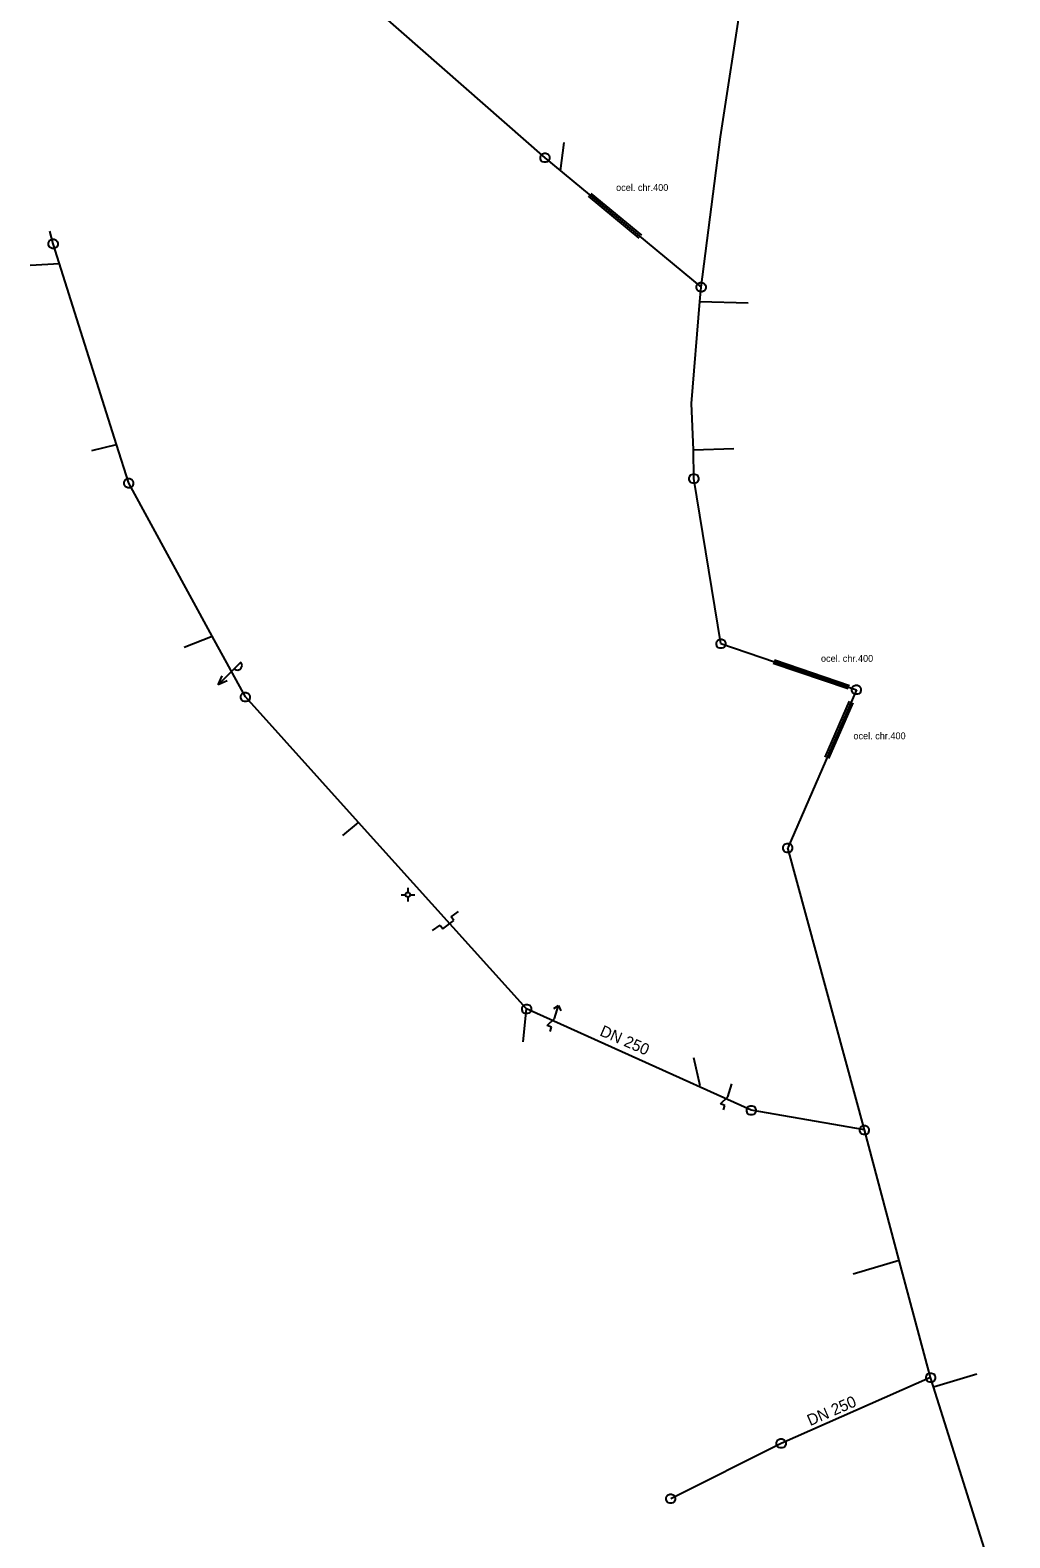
# Model space of a CAD drawing. Extents: x -717256 to -716843, y -1145423 to -1142840.
# Drawn here: x -717224 to -717116.2, y -1144391.3 to -1144225.5 of the extents above; entities that cross this region are included whole.
import ezdxf

# ---------------------------------------------------------------- set-up
doc = ezdxf.new("R2010")
doc.units = 0
for name, color, linetype in [('Vrstva 29', 7, 'Continuous'), ('Vrstva 30', 7, 'Continuous'), ('Vrstva 31', 7, 'Continuous'), ('Vrstva 9', 7, 'Continuous')]:
    doc.layers.add(name, color=color, linetype=linetype)

msp = doc.modelspace()

# ---------------------------------------------------------------- linework, layer by layer
at = {"layer": 'Vrstva 29'}
for p, q in [((-717162.308, -1144243.433), (-717156.744, -1144248.041)), ((-717156.999, -1144248.349), (-717162.564, -1144243.741)), ((-717142.113, -1144294.741), (-717133.851, -1144297.547)), ((-717133.98, -1144297.925), (-717142.242, -1144295.12)), ((-717136.528, -1144305.439), (-717133.86, -1144299.289)), ((-717133.493, -1144299.448), (-717136.161, -1144305.598))]:
    msp.add_line(p, q, dxfattribs=at)
at = {"layer": 'Vrstva 30'}
for p, q in [((-717193.377, -1144216.671), (-717167.355, -1144239.514)), ((-717148.036, -1144237.218), (-717145.608, -1144221.417)), ((-717150.172, -1144253.744), (-717148.036, -1144237.218)), ((-717167.855, -1144239.414), (-717167.805, -1144239.264)), ((-717167.855, -1144239.614), (-717167.855, -1144239.414)), ((-717167.755, -1144239.864), (-717167.855, -1144239.614)), ((-717167.805, -1144239.264), (-717167.705, -1144239.114)), ((-717167.605, -1144239.964), (-717167.755, -1144239.864)), ((-717167.705, -1144239.114), (-717167.455, -1144239.014)), ((-717167.455, -1144240.014), (-717167.605, -1144239.964)), ((-717167.455, -1144239.014), (-717167.255, -1144239.014)), ((-717167.255, -1144240.014), (-717167.455, -1144240.014)), ((-717167.355, -1144239.514), (-717150.172, -1144253.744)), ((-717167.255, -1144239.014), (-717167.005, -1144239.114)), ((-717167.105, -1144239.964), (-717167.255, -1144240.014)), ((-717166.955, -1144239.864), (-717167.105, -1144239.964)), ((-717167.005, -1144239.114), (-717166.905, -1144239.264)), ((-717166.855, -1144239.614), (-717166.955, -1144239.864)), ((-717166.905, -1144239.264), (-717166.855, -1144239.414)), ((-717166.855, -1144239.414), (-717166.855, -1144239.614)), ((-717221.9, -1144248.73), (-717221.8, -1144248.58)), ((-717221.8, -1144248.58), (-717221.55, -1144248.48)), ((-717221.55, -1144248.48), (-717221.35, -1144248.48)), ((-717221.35, -1144248.48), (-717221.1, -1144248.58)), ((-717221.1, -1144248.58), (-717221, -1144248.73)), ((-717221.95, -1144248.88), (-717221.9, -1144248.73)), ((-717221.95, -1144249.08), (-717221.95, -1144248.88)), ((-717221.85, -1144249.33), (-717221.95, -1144249.08)), ((-717221.7, -1144249.43), (-717221.85, -1144249.33)), ((-717221.55, -1144249.48), (-717221.7, -1144249.43)), ((-717221.35, -1144249.48), (-717221.55, -1144249.48)), ((-717214.472, -1144271.053), (-717221.45, -1144248.98)), ((-717221.2, -1144249.43), (-717221.35, -1144249.48)), ((-717221.05, -1144249.33), (-717221.2, -1144249.43)), ((-717220.95, -1144249.08), (-717221.05, -1144249.33)), ((-717221, -1144248.73), (-717220.95, -1144248.88)), ((-717220.95, -1144248.88), (-717220.95, -1144249.08)), ((-717150.672, -1144253.644), (-717150.622, -1144253.494)), ((-717150.622, -1144253.494), (-717150.522, -1144253.344)), ((-717150.522, -1144253.344), (-717150.272, -1144253.244)), ((-717150.272, -1144253.244), (-717150.072, -1144253.244)), ((-717150.072, -1144253.244), (-717149.822, -1144253.344)), ((-717149.822, -1144253.344), (-717149.722, -1144253.494)), ((-717149.722, -1144253.494), (-717149.672, -1144253.644)), ((-717150.672, -1144253.844), (-717150.672, -1144253.644)), ((-717150.572, -1144254.094), (-717150.672, -1144253.844)), ((-717150.422, -1144254.194), (-717150.572, -1144254.094)), ((-717150.272, -1144254.244), (-717150.422, -1144254.194)), ((-717150.315, -1144255.34), (-717150.172, -1144253.744)), ((-717150.072, -1144254.244), (-717150.272, -1144254.244)), ((-717149.922, -1144254.194), (-717150.072, -1144254.244)), ((-717149.772, -1144254.094), (-717149.922, -1144254.194)), ((-717149.672, -1144253.844), (-717149.772, -1144254.094)), ((-717149.672, -1144253.644), (-717149.672, -1144253.844)), ((-717151.218, -1144266.557), (-717150.315, -1144255.34)), ((-717151.004, -1144271.637), (-717151.218, -1144266.557)), ((-717213.13, -1144275.3), (-717214.472, -1144271.053)), ((-717150.974, -1144274.805), (-717151.004, -1144271.637)), ((-717213.63, -1144275.2), (-717213.58, -1144275.05)), ((-717213.58, -1144275.05), (-717213.48, -1144274.9)), ((-717213.48, -1144274.9), (-717213.23, -1144274.8)), ((-717213.23, -1144274.8), (-717213.03, -1144274.8)), ((-717213.03, -1144274.8), (-717212.78, -1144274.9)), ((-717212.78, -1144274.9), (-717212.68, -1144275.05)), ((-717212.68, -1144275.05), (-717212.63, -1144275.2)), ((-717151.474, -1144274.705), (-717151.424, -1144274.555)), ((-717151.474, -1144274.905), (-717151.474, -1144274.705)), ((-717151.374, -1144275.155), (-717151.474, -1144274.905)), ((-717151.424, -1144274.555), (-717151.324, -1144274.405)), ((-717151.224, -1144275.255), (-717151.374, -1144275.155)), ((-717151.324, -1144274.405), (-717151.074, -1144274.305)), ((-717151.074, -1144274.305), (-717150.874, -1144274.305)), ((-717147.999, -1144292.954), (-717150.974, -1144274.805)), ((-717150.874, -1144274.305), (-717150.624, -1144274.405)), ((-717150.574, -1144275.155), (-717150.724, -1144275.255)), ((-717150.624, -1144274.405), (-717150.524, -1144274.555)), ((-717150.474, -1144274.905), (-717150.574, -1144275.155)), ((-717150.524, -1144274.555), (-717150.474, -1144274.705)), ((-717150.474, -1144274.705), (-717150.474, -1144274.905)), ((-717213.63, -1144275.4), (-717213.63, -1144275.2)), ((-717213.53, -1144275.65), (-717213.63, -1144275.4)), ((-717213.38, -1144275.75), (-717213.53, -1144275.65)), ((-717213.23, -1144275.8), (-717213.38, -1144275.75)), ((-717213.03, -1144275.8), (-717213.23, -1144275.8)), ((-717203.943, -1144292.139), (-717213.13, -1144275.3)), ((-717212.88, -1144275.75), (-717213.03, -1144275.8)), ((-717212.73, -1144275.65), (-717212.88, -1144275.75)), ((-717212.63, -1144275.4), (-717212.73, -1144275.65)), ((-717212.63, -1144275.2), (-717212.63, -1144275.4)), ((-717151.074, -1144275.305), (-717151.224, -1144275.255)), ((-717150.874, -1144275.305), (-717151.074, -1144275.305)), ((-717150.724, -1144275.255), (-717150.874, -1144275.305)), ((-717200.3, -1144298.82), (-717203.943, -1144292.139)), ((-717148.499, -1144292.854), (-717148.449, -1144292.704)), ((-717148.499, -1144293.054), (-717148.499, -1144292.854)), ((-717148.399, -1144293.304), (-717148.499, -1144293.054)), ((-717148.449, -1144292.704), (-717148.349, -1144292.554)), ((-717148.249, -1144293.404), (-717148.399, -1144293.304)), ((-717148.349, -1144292.554), (-717148.099, -1144292.454)), ((-717148.099, -1144293.454), (-717148.249, -1144293.404)), ((-717148.099, -1144292.454), (-717147.899, -1144292.454)), ((-717147.999, -1144292.954), (-717133.087, -1144298.018)), ((-717147.899, -1144292.454), (-717147.649, -1144292.554)), ((-717147.749, -1144293.404), (-717147.899, -1144293.454)), ((-717147.599, -1144293.304), (-717147.749, -1144293.404)), ((-717147.649, -1144292.554), (-717147.549, -1144292.704)), ((-717147.499, -1144293.054), (-717147.599, -1144293.304)), ((-717147.549, -1144292.704), (-717147.499, -1144292.854)), ((-717147.499, -1144292.854), (-717147.499, -1144293.054)), ((-717147.899, -1144293.454), (-717148.099, -1144293.454)), ((-717200.65, -1144298.42), (-717200.4, -1144298.32)), ((-717200.4, -1144298.32), (-717200.2, -1144298.32)), ((-717200.2, -1144298.32), (-717199.95, -1144298.42)), ((-717133.087, -1144298.018), (-717140.652, -1144315.421)), ((-717133.587, -1144297.918), (-717133.537, -1144297.768)), ((-717133.587, -1144298.118), (-717133.587, -1144297.918)), ((-717133.487, -1144298.368), (-717133.587, -1144298.118)), ((-717133.537, -1144297.768), (-717133.437, -1144297.618)), ((-717133.337, -1144298.468), (-717133.487, -1144298.368)), ((-717133.437, -1144297.618), (-717133.187, -1144297.518)), ((-717133.187, -1144297.518), (-717132.987, -1144297.518)), ((-717132.987, -1144297.518), (-717132.737, -1144297.618)), ((-717132.687, -1144298.368), (-717132.837, -1144298.468)), ((-717132.737, -1144297.618), (-717132.637, -1144297.768)), ((-717132.587, -1144298.118), (-717132.687, -1144298.368)), ((-717132.637, -1144297.768), (-717132.587, -1144297.918)), ((-717132.587, -1144297.918), (-717132.587, -1144298.118)), ((-717200.8, -1144298.72), (-717200.75, -1144298.57)), ((-717200.8, -1144298.92), (-717200.8, -1144298.72)), ((-717200.7, -1144299.17), (-717200.8, -1144298.92)), ((-717200.75, -1144298.57), (-717200.65, -1144298.42)), ((-717200.55, -1144299.27), (-717200.7, -1144299.17)), ((-717200.4, -1144299.32), (-717200.55, -1144299.27)), ((-717200.2, -1144299.32), (-717200.4, -1144299.32)), ((-717187.844, -1144312.636), (-717200.3, -1144298.82)), ((-717200.05, -1144299.27), (-717200.2, -1144299.32)), ((-717199.9, -1144299.17), (-717200.05, -1144299.27)), ((-717199.95, -1144298.42), (-717199.85, -1144298.57)), ((-717199.8, -1144298.92), (-717199.9, -1144299.17)), ((-717199.85, -1144298.57), (-717199.8, -1144298.72)), ((-717199.8, -1144298.72), (-717199.8, -1144298.92)), ((-717133.187, -1144298.518), (-717133.337, -1144298.468)), ((-717132.987, -1144298.518), (-717133.187, -1144298.518)), ((-717132.837, -1144298.468), (-717132.987, -1144298.518)), ((-717169.37, -1144333.13), (-717187.844, -1144312.636)), ((-717141.002, -1144315.021), (-717140.752, -1144314.921)), ((-717140.752, -1144314.921), (-717140.552, -1144314.921)), ((-717140.552, -1144314.921), (-717140.302, -1144315.021)), ((-717141.152, -1144315.321), (-717141.102, -1144315.171)), ((-717141.152, -1144315.521), (-717141.152, -1144315.321)), ((-717141.052, -1144315.771), (-717141.152, -1144315.521)), ((-717141.102, -1144315.171), (-717141.002, -1144315.021)), ((-717140.902, -1144315.871), (-717141.052, -1144315.771)), ((-717140.752, -1144315.921), (-717140.902, -1144315.871)), ((-717140.552, -1144315.921), (-717140.752, -1144315.921)), ((-717132.208, -1144346.446), (-717140.652, -1144315.421)), ((-717140.402, -1144315.871), (-717140.552, -1144315.921)), ((-717140.252, -1144315.771), (-717140.402, -1144315.871)), ((-717140.302, -1144315.021), (-717140.202, -1144315.171)), ((-717140.152, -1144315.521), (-717140.252, -1144315.771)), ((-717140.202, -1144315.171), (-717140.152, -1144315.321)), ((-717140.152, -1144315.321), (-717140.152, -1144315.521)), ((-717169.87, -1144333.03), (-717169.82, -1144332.88)), ((-717169.87, -1144333.23), (-717169.87, -1144333.03)), ((-717169.82, -1144332.88), (-717169.72, -1144332.73)), ((-717169.72, -1144332.73), (-717169.47, -1144332.63)), ((-717169.47, -1144332.63), (-717169.27, -1144332.63)), ((-717144.66, -1144344.28), (-717169.37, -1144333.13)), ((-717169.27, -1144332.63), (-717169.02, -1144332.73)), ((-717169.02, -1144332.73), (-717168.92, -1144332.88)), ((-717168.92, -1144332.88), (-717168.87, -1144333.03)), ((-717168.87, -1144333.03), (-717168.87, -1144333.23)), ((-717169.77, -1144333.48), (-717169.87, -1144333.23)), ((-717169.62, -1144333.58), (-717169.77, -1144333.48)), ((-717169.47, -1144333.63), (-717169.62, -1144333.58)), ((-717169.27, -1144333.63), (-717169.47, -1144333.63)), ((-717169.12, -1144333.58), (-717169.27, -1144333.63)), ((-717168.97, -1144333.48), (-717169.12, -1144333.58)), ((-717168.87, -1144333.23), (-717168.97, -1144333.48)), ((-717145.16, -1144344.18), (-717145.11, -1144344.03)), ((-717145.16, -1144344.38), (-717145.16, -1144344.18)), ((-717145.06, -1144344.63), (-717145.16, -1144344.38)), ((-717145.11, -1144344.03), (-717145.01, -1144343.88)), ((-717144.91, -1144344.73), (-717145.06, -1144344.63)), ((-717145.01, -1144343.88), (-717144.76, -1144343.78)), ((-717144.76, -1144344.78), (-717144.91, -1144344.73)), ((-717144.76, -1144343.78), (-717144.56, -1144343.78)), ((-717144.56, -1144344.78), (-717144.76, -1144344.78)), ((-717132.208, -1144346.446), (-717144.66, -1144344.28)), ((-717144.56, -1144343.78), (-717144.31, -1144343.88)), ((-717144.41, -1144344.73), (-717144.56, -1144344.78)), ((-717144.26, -1144344.63), (-717144.41, -1144344.73)), ((-717144.31, -1144343.88), (-717144.21, -1144344.03)), ((-717144.16, -1144344.38), (-717144.26, -1144344.63)), ((-717144.21, -1144344.03), (-717144.16, -1144344.18)), ((-717144.16, -1144344.18), (-717144.16, -1144344.38)), ((-717132.708, -1144346.346), (-717132.658, -1144346.196)), ((-717132.708, -1144346.546), (-717132.708, -1144346.346)), ((-717132.658, -1144346.196), (-717132.558, -1144346.046)), ((-717132.558, -1144346.046), (-717132.308, -1144345.946)), ((-717132.308, -1144345.946), (-717132.108, -1144345.946)), ((-717128.394, -1144360.809), (-717132.208, -1144346.446)), ((-717132.108, -1144345.946), (-717131.858, -1144346.046)), ((-717131.858, -1144346.046), (-717131.758, -1144346.196)), ((-717131.758, -1144346.196), (-717131.708, -1144346.346)), ((-717131.708, -1144346.346), (-717131.708, -1144346.546)), ((-717132.608, -1144346.796), (-717132.708, -1144346.546)), ((-717132.458, -1144346.896), (-717132.608, -1144346.796)), ((-717132.308, -1144346.946), (-717132.458, -1144346.896)), ((-717132.108, -1144346.946), (-717132.308, -1144346.946)), ((-717131.958, -1144346.896), (-717132.108, -1144346.946)), ((-717131.808, -1144346.796), (-717131.958, -1144346.896)), ((-717131.708, -1144346.546), (-717131.808, -1144346.796)), ((-717124.925, -1144373.683), (-717128.394, -1144360.809)), ((-717124.925, -1144373.683), (-717141.37, -1144380.91)), ((-717125.425, -1144373.583), (-717125.375, -1144373.433)), ((-717125.425, -1144373.783), (-717125.425, -1144373.583)), ((-717125.325, -1144374.033), (-717125.425, -1144373.783)), ((-717125.375, -1144373.433), (-717125.275, -1144373.283)), ((-717125.175, -1144374.133), (-717125.325, -1144374.033)), ((-717125.275, -1144373.283), (-717125.025, -1144373.183)), ((-717125.025, -1144374.183), (-717125.175, -1144374.133)), ((-717125.025, -1144373.183), (-717124.825, -1144373.183)), ((-717124.825, -1144374.183), (-717125.025, -1144374.183)), ((-717124.609, -1144374.682), (-717124.925, -1144373.683)), ((-717124.825, -1144373.183), (-717124.575, -1144373.283)), ((-717124.675, -1144374.133), (-717124.825, -1144374.183)), ((-717124.525, -1144374.033), (-717124.675, -1144374.133)), ((-717116.213, -1144401.308), (-717124.609, -1144374.682)), ((-717124.575, -1144373.283), (-717124.475, -1144373.433)), ((-717124.425, -1144373.783), (-717124.525, -1144374.033)), ((-717124.475, -1144373.433), (-717124.425, -1144373.583)), ((-717124.425, -1144373.583), (-717124.425, -1144373.783)), ((-717141.37, -1144380.91), (-717153.52, -1144387)), ((-717141.87, -1144380.81), (-717141.82, -1144380.66)), ((-717141.87, -1144381.01), (-717141.87, -1144380.81)), ((-717141.77, -1144381.26), (-717141.87, -1144381.01)), ((-717141.82, -1144380.66), (-717141.72, -1144380.51)), ((-717141.62, -1144381.36), (-717141.77, -1144381.26)), ((-717141.72, -1144380.51), (-717141.47, -1144380.41)), ((-717141.47, -1144380.41), (-717141.27, -1144380.41)), ((-717141.27, -1144380.41), (-717141.02, -1144380.51)), ((-717140.97, -1144381.26), (-717141.12, -1144381.36)), ((-717141.02, -1144380.51), (-717140.92, -1144380.66)), ((-717140.87, -1144381.01), (-717140.97, -1144381.26)), ((-717140.92, -1144380.66), (-717140.87, -1144380.81)), ((-717140.87, -1144380.81), (-717140.87, -1144381.01)), ((-717141.47, -1144381.41), (-717141.62, -1144381.36)), ((-717141.27, -1144381.41), (-717141.47, -1144381.41)), ((-717141.12, -1144381.36), (-717141.27, -1144381.41)), ((-717154.02, -1144386.9), (-717153.97, -1144386.75)), ((-717154.02, -1144387.1), (-717154.02, -1144386.9)), ((-717153.92, -1144387.35), (-717154.02, -1144387.1)), ((-717153.97, -1144386.75), (-717153.87, -1144386.6)), ((-717153.77, -1144387.45), (-717153.92, -1144387.35)), ((-717153.87, -1144386.6), (-717153.62, -1144386.5)), ((-717153.62, -1144387.5), (-717153.77, -1144387.45)), ((-717153.62, -1144386.5), (-717153.42, -1144386.5)), ((-717153.42, -1144387.5), (-717153.62, -1144387.5)), ((-717153.42, -1144386.5), (-717153.17, -1144386.6)), ((-717153.27, -1144387.45), (-717153.42, -1144387.5)), ((-717153.12, -1144387.35), (-717153.27, -1144387.45)), ((-717153.17, -1144386.6), (-717153.07, -1144386.75)), ((-717153.02, -1144387.1), (-717153.12, -1144387.35)), ((-717153.07, -1144386.75), (-717153.02, -1144386.9)), ((-717153.02, -1144386.9), (-717153.02, -1144387.1))]:
    msp.add_line(p, q, dxfattribs=at)
at = {"layer": 'Vrstva 31'}
for p, q in [((-717165.638, -1144240.935), (-717165.243, -1144237.837)), ((-717221.45, -1144248.98), (-717221.82, -1144247.57)), ((-717223.98, -1144251.33), (-717220.74, -1144251.16)), ((-717150.315, -1144255.34), (-717145, -1144255.481)), ((-717217.18, -1144271.71), (-717214.472, -1144271.053)), ((-717151.004, -1144271.637), (-717146.571, -1144271.494)), ((-717207.03, -1144293.34), (-717203.943, -1144292.139)), ((-717189.57, -1144314.06), (-717187.844, -1144312.636)), ((-717169.74, -1144336.76), (-717169.37, -1144333.13)), ((-717150.285, -1144341.602), (-717150.985, -1144338.509)), ((-717128.394, -1144360.809), (-717133.436, -1144362.296)), ((-717124.609, -1144374.682), (-717119.836, -1144373.257))]:
    msp.add_line(p, q, dxfattribs=at)
at = {"layer": 'Vrstva 9'}
for p, q in [((-717200.822, -1144294.992), (-717203.297, -1144297.467)), ((-717200.751, -1144295.063), (-717200.822, -1144294.992)), ((-717200.681, -1144295.204), (-717200.751, -1144295.063)), ((-717203.297, -1144297.467), (-717202.873, -1144296.477)), ((-717201.529, -1144295.699), (-717201.458, -1144295.77)), ((-717201.458, -1144295.77), (-717201.317, -1144295.841)), ((-717201.317, -1144295.841), (-717201.14, -1144295.876)), ((-717201.14, -1144295.876), (-717200.893, -1144295.77)), ((-717200.893, -1144295.77), (-717200.751, -1144295.628)), ((-717200.751, -1144295.628), (-717200.645, -1144295.381)), ((-717200.645, -1144295.381), (-717200.681, -1144295.204)), ((-717202.307, -1144297.043), (-717203.297, -1144297.467)), ((-717182.427, -1144319.822), (-717182.427, -1144320.321)), ((-717183.177, -1144320.572), (-717182.678, -1144320.572)), ((-717182.43, -1144320.57), (-717182.43, -1144320.574)), ((-717182.425, -1144320.57), (-717182.43, -1144320.57)), ((-717182.43, -1144320.574), (-717182.425, -1144320.574)), ((-717182.427, -1144320.822), (-717182.427, -1144321.321)), ((-717182.425, -1144320.574), (-717182.425, -1144320.57)), ((-717182.177, -1144320.572), (-717181.678, -1144320.572)), ((-717177.683, -1144323.019), (-717176.874, -1144322.431)), ((-717177.389, -1144323.423), (-717177.683, -1144323.019)), ((-717179.705, -1144324.488), (-717178.896, -1144323.9)), ((-717178.896, -1144323.9), (-717178.602, -1144324.305)), ((-717178.602, -1144324.305), (-717177.389, -1144323.423)), ((-717166.381, -1144333.095), (-717165.846, -1144332.743)), ((-717166.31, -1144334.17), (-717165.846, -1144332.743)), ((-717165.846, -1144332.743), (-717165.62, -1144333.342)), ((-717167.094, -1144334.966), (-717166.31, -1144334.17)), ((-717166.619, -1144335.121), (-717167.094, -1144334.966)), ((-717166.773, -1144335.596), (-717166.619, -1144335.121)), ((-717147.25, -1144342.79), (-717146.786, -1144341.363)), ((-717148.034, -1144343.586), (-717147.25, -1144342.79)), ((-717147.559, -1144343.741), (-717148.034, -1144343.586)), ((-717147.713, -1144344.216), (-717147.559, -1144343.741))]:
    msp.add_line(p, q, dxfattribs=at)
msp.add_circle((-717182.427, -1144320.572), 0.25, dxfattribs=at)

# ---------------------------------------------------------------- texts
at = {"layer": 'Vrstva 30'}
for p in [(-717159.524, -1144243.159), (-717136.989, -1144294.957), (-717133.419, -1144303.47)]:
    msp.add_text('ocel. chr.400', height=0.74999, dxfattribs=at).set_placement(p)
for rotation, p in [(336.6, (-717161.416, -1144336.018)), (23.4, (-717138.178, -1144379.02))]:
    msp.add_text('DN 250', height=1.25, rotation=rotation, dxfattribs=at).set_placement(p)

doc.saveas('drawing.dxf')
